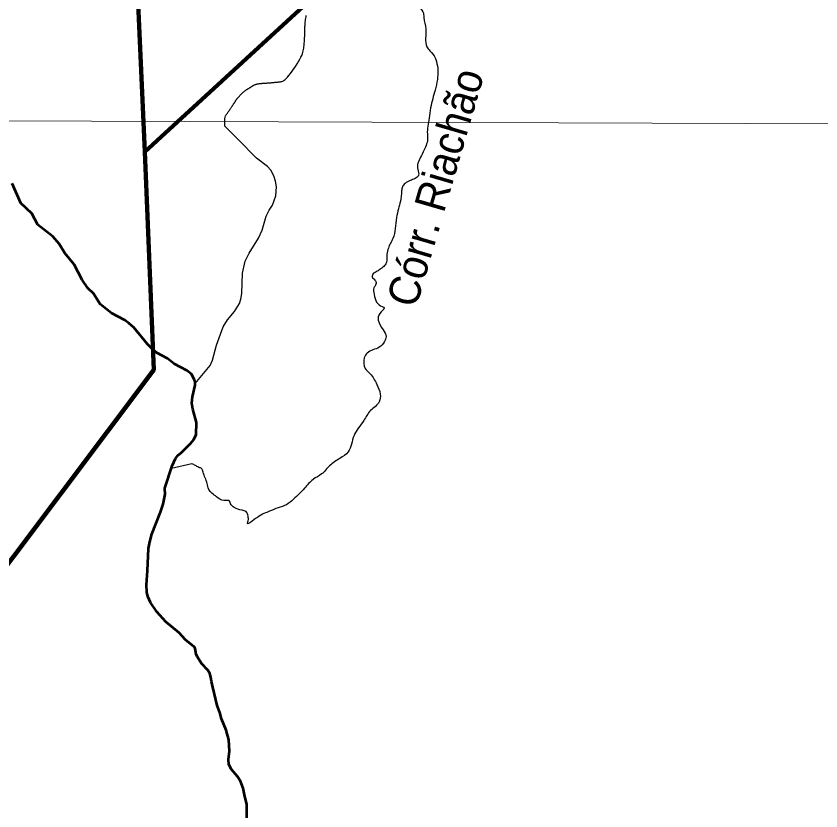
# Model space of a CAD drawing. Extents: x 553962 to 842807, y 8883888 to 9032388.
# Drawn here: x 703445 to 716356, y 8938306 to 8951050 of the extents above; entities that cross this region are included whole.
import ezdxf

# ---------------------------------------------------------------- set-up
doc = ezdxf.new("R2010")
doc.units = 0
doc.header["$LTSCALE"] = 20
for name, color, linetype, lineweight in [('1', 7, 'Continuous', 13), ('24', 7, 'Continuous', 25), ('9', 7, 'Continuous', 90)]:
    doc.layers.add(name, color=color, linetype=linetype, lineweight=lineweight)
doc.layers.add('49', color=7, linetype='Continuous')

msp = doc.modelspace()

# ---------------------------------------------------------------- linework, layer by layer
at = {"layer": '1'}
msp.add_line((565315.27, 8949866.81), (791497.68, 8949052.23), dxfattribs=at)
at = {"layer": '24'}
msp.add_line((706264.71, 8943870.48), (705937.76, 8943795.82), dxfattribs=at)
for points in [[(707335.33, 8949965.78), (707343.36, 8949967.03), (707351.5, 8949968.16), (707359.72, 8949969.19), (707368, 8949970.13), (707376.3, 8949970.99), (707384.61, 8949971.77), (707392.94, 8949972.49), (707401.31, 8949973.15), (707409.73, 8949973.76), (707418.22, 8949974.34), (707426.81, 8949974.89), (707435.51, 8949975.42), (707444.34, 8949975.94), (707453.3, 8949976.45), (707462.39, 8949976.98), (707471.58, 8949977.52), (707480.82, 8949978.09), (707490.11, 8949978.7), (707499.4, 8949979.35), (707508.68, 8949980.06), (707517.91, 8949980.83), (707527.08, 8949981.68), (707536.25, 8949982.59), (707545.5, 8949983.55), (707554.9, 8949984.57), (707564.52, 8949985.61), (707574.43, 8949986.68), (707584.72, 8949987.77), (707595.45, 8949988.86), (707606.67, 8949989.95), (707618.28, 8949991.05), (707630.14, 8949992.16), (707642.14, 8949993.3), (707654.13, 8949994.47), (707666, 8949995.7), (707677.61, 8949996.98), (707688.83, 8949998.33), (707699.63, 8949999.87), (707710.37, 8950002.21), (707721.51, 8950006.03), (707733.52, 8950012.07), (707746.84, 8950021.02), (707761.95, 8950033.6), (707779.31, 8950050.5), (707799.36, 8950072.45), (707822.35, 8950099.85), (707847.63, 8950131.86), (707874.31, 8950167.33), (707901.5, 8950205.14), (707928.34, 8950244.13), (707953.94, 8950283.17), (707977.41, 8950321.12), (707997.88, 8950356.84), (708014.69, 8950389.43), (708028.08, 8950419.07), (708038.49, 8950446.16), (708046.4, 8950471.11), (708052.25, 8950494.34), (708056.51, 8950516.26), (708059.63, 8950537.28), (708062.07, 8950557.81), (708064.21, 8950578.17), (708066.14, 8950598.25), (708067.85, 8950617.86), (708069.37, 8950636.78), (708070.7, 8950654.81), (708071.84, 8950671.75), (708072.8, 8950687.4), (708073.59, 8950701.55), (708074.22, 8950714.07), (708074.7, 8950725.12), (708075.07, 8950734.96), (708075.33, 8950743.81), (708075.52, 8950751.93), (708075.64, 8950759.54), (708075.73, 8950766.9), (708075.79, 8950774.24), (708075.86, 8950781.77), (708075.94, 8950789.6), (708076.04, 8950797.79), (708076.17, 8950806.44), (708076.34, 8950815.6), (708076.57, 8950825.35), (708076.85, 8950835.77), (708077.21, 8950846.93), (708077.66, 8950858.91), (708078.23, 8950871.77), (708078.98, 8950885.59), (708079.95, 8950900.45), (708081.18, 8950916.42), (708082.74, 8950933.57), (708084.66, 8950951.98), (708086.98, 8950971.72), (708089.73, 8950992.81), (708092.74, 8951015.07), (708095.84, 8951038.28), (708098.83, 8951062.2)], [(707103.04, 8949843.33), (707109.6, 8949848.42), (707116.17, 8949853.29), (707122.74, 8949857.98), (707129.33, 8949862.49), (707135.95, 8949866.86), (707142.6, 8949871.13), (707149.3, 8949875.31), (707156.06, 8949879.43), (707162.88, 8949883.52), (707169.76, 8949887.61), (707176.67, 8949891.69), (707183.56, 8949895.75), (707190.39, 8949899.78), (707197.11, 8949903.78), (707203.66, 8949907.73), (707210.02, 8949911.63), (707216.12, 8949915.47), (707221.95, 8949919.23), (707227.54, 8949922.91), (707232.96, 8949926.51), (707238.28, 8949930), (707243.57, 8949933.38), (707248.88, 8949936.64), (707254.28, 8949939.76), (707259.84, 8949942.75), (707265.61, 8949945.59), (707271.6, 8949948.28), (707277.81, 8949950.82), (707284.24, 8949953.21), (707290.89, 8949955.45), (707297.77, 8949957.54), (707304.86, 8949959.48), (707312.18, 8949961.27), (707319.71, 8949962.91), (707327.44, 8949964.41), (707335.33, 8949965.78)], [(707005.53, 8949071.85), (706794.49, 8949287.1), (706791.81, 8949335.96), (706791.81, 8949375.11), (706794.08, 8949405.97), (706798.26, 8949429.95), (706803.94, 8949448.46), (706810.75, 8949462.93), (706818.3, 8949474.75), (706826.2, 8949485.34), (706834.12, 8949495.87), (706841.96, 8949506.49), (706849.65, 8949517.1), (706857.15, 8949527.61), (706864.41, 8949537.91), (706871.38, 8949547.91), (706878, 8949557.52), (706884.22, 8949566.64), (706890.01, 8949575.2), (706895.41, 8949583.23), (706900.47, 8949590.8), (706905.25, 8949597.97), (706909.8, 8949604.82), (706914.18, 8949611.39), (706918.45, 8949617.77), (706922.67, 8949624), (706926.87, 8949630.15), (706931.04, 8949636.22), (706935.15, 8949642.19), (706939.18, 8949648.06), (706943.1, 8949653.83), (706946.88, 8949659.47), (706950.49, 8949664.98), (706953.9, 8949670.36), (706957.11, 8949675.6), (706960.17, 8949680.73), (706963.15, 8949685.79), (706966.13, 8949690.8), (706969.19, 8949695.82), (706972.4, 8949700.88), (706975.82, 8949706), (706979.55, 8949711.24), (706983.63, 8949716.61), (706988.02, 8949722.1), (706992.67, 8949727.71), (706997.53, 8949733.41), (707002.54, 8949739.18), (707007.64, 8949745), (707012.77, 8949750.86), (707017.89, 8949756.74), (707022.95, 8949762.63), (707027.98, 8949768.51), (707033, 8949774.4), (707038.06, 8949780.28), (707043.19, 8949786.16), (707048.44, 8949792.04), (707053.83, 8949797.93), (707059.41, 8949803.8), (707065.2, 8949809.68), (707071.18, 8949815.52), (707077.33, 8949821.31), (707083.62, 8949827.01), (707090.02, 8949832.6), (707096.5, 8949838.05), (707103.04, 8949843.33)], [(706318.13, 8945157.75), (706558.53, 8945449.14), (706593.78, 8945534.08), (706659.09, 8945772.72), (706765.23, 8946065.51), (706837.04, 8946180.29), (706950.78, 8946315.39), (707030.06, 8946442.17), (707051.34, 8946511.72), (707065.53, 8946600.05), (707074.41, 8946928.92), (707120.5, 8947121.76), (707182.67, 8947250.28), (707335.36, 8947487.7), (707390.24, 8947616.93), (707459.21, 8947840.21), (707507.03, 8947940.81), (707556.36, 8948018.23), (707613.41, 8948168.47), (707621.56, 8948310.71), (707609.07, 8948405.14), (707580.34, 8948486.25), (707531.19, 8948578.03), (707480.25, 8948638.26), (707302.29, 8948774.04), (707005.53, 8949071.85)]]:
    msp.add_lwpolyline(points, dxfattribs=at)
at = {"layer": '24', "lineweight": 53}
for points in [[(705832.84, 8943474.06), (705832.25, 8943483.44), (705948.73, 8943839.02), (706001.06, 8943954.51), (706040.19, 8944007.23), (706100.5, 8944053.43), (706243.07, 8944196.48), (706294.62, 8944261.85), (706335.28, 8944339.08), (706341.06, 8944535.41), (706282.44, 8944747.12), (706266.05, 8944843.36), (706272.33, 8944945.56), (706319.27, 8945130.16), (706317, 8945185.35), (706303.96, 8945230.7), (706260.77, 8945306.24), (706182.61, 8945367.1), (705978.73, 8945474.39), (705872.53, 8945557.87), (705704.45, 8945652.52), (705622.37, 8945719.46), (705553.15, 8945790.51), (705334.08, 8946058.71), (705261.14, 8946123.78), (705190.94, 8946173.28), (704977.76, 8946288.61), (704792.63, 8946429.02), (704685.44, 8946599.97), (704597.4, 8946688.7), (704507.14, 8946819.4), (704375.46, 8947069.73), (704224.77, 8947248.33), (704136.74, 8947399.1), (704031.96, 8947515.03), (703791.65, 8947703.97), (703699.7, 8947883.19), (703521.31, 8948048.58), (703380.43, 8948367.76)], [(707112.44, 8938537.61), (707087.72, 8938670.62), (707047.46, 8938783.25), (706998.9, 8938860.14), (706901.05, 8938969.18), (706857.7, 8939050.01), (706854.78, 8939130.07), (706866.72, 8939261.74), (706857.82, 8939446.33), (706814.82, 8939599.79), (706742.16, 8939780.93), (706712.89, 8939886.31), (706669.76, 8939997.22), (706579.57, 8940379.37), (706570.62, 8940449.86), (706551.48, 8940509.27), (706520.24, 8940562.66), (706419.45, 8940668.77), (706347.48, 8940779.51), (706331.35, 8940817.84), (706319.65, 8940908.81), (706302.5, 8940937.07), (706163, 8941049.89), (706059.84, 8941158.75), (705847.86, 8941335.15), (705702.68, 8941495.44), (705602.13, 8941646.25), (705560.76, 8941741.3), (705543.53, 8941811.47), (705536.27, 8941930.57), (705555.45, 8942152.93), (705571.33, 8942515.57), (705588.83, 8942621.53), (705620.58, 8942742.31), (705760.38, 8943097.48), (705802.31, 8943224.23), (705838.49, 8943384.29), (705832.84, 8943474.06)], [(706694.7, 8936277.48), (706830.5, 8936420.38), (706877.21, 8936486.3), (706914.59, 8936562.19), (706925.82, 8936622.03), (706895.34, 8936909.29), (706910.97, 8937033.72), (706943.27, 8937127.24), (707023.24, 8937296.13), (707124.83, 8937469.74), (707160.22, 8937564.47), (707176.93, 8937639.28), (707157.27, 8937927.69), (707160.03, 8938043.54), (707144.19, 8938159.46), (707144.94, 8938415.97), (707112.44, 8938537.61)]]:
    msp.add_lwpolyline(points, dxfattribs=at)
at = {"layer": '24'}
for points in [[(710764.45, 8952700.73), (710808.55, 8952628.53), (710796.52, 8952588.41), (710732.37, 8952468.07), (710692.28, 8952383.84), (710547.94, 8952271.52), (710451.72, 8952187.28), (710375.54, 8952135.13), (710311.39, 8952030.84), (710235.21, 8951906.48), (710171.06, 8951786.14), (710138.99, 8951641.74), (710082.85, 8951517.38), (709994.65, 8951429.13), (709898.42, 8951364.95), (709874.37, 8951284.73), (709890.4, 8951220.54), (709970.59, 8951120.26), (709986.63, 8951028), (710018.7, 8950843.48), (710034.74, 8950558.67), (710082.85, 8950490.48), (710167.05, 8950382.17), (710187.1, 8950322), (710211.15, 8950177.59), (710203.14, 8950033.18), (710167.06, 8949864.71), (710094.89, 8949579.9), (710070.83, 8949411.42), (710042.76, 8949159.91), (710046.77, 8949099.74), (710030.74, 8948999.46), (709990.64, 8948903.19), (709934.51, 8948786.86), (709890.41, 8948690.59), (709890.41, 8948590.3), (709902.44, 8948498.04), (709846.3, 8948445.89), (709766.12, 8948413.8), (709685.93, 8948365.67), (709641.83, 8948313.52), (709629.8, 8948249.34), (709609.75, 8948080.86), (709577.68, 8947960.52), (709549.61, 8947820.12), (709525.55, 8947643.62), (709489.47, 8947483.17), (709449.38, 8947406.95), (709417.3, 8947330.74), (709393.25, 8947226.44), (709385.23, 8947106.1), (709357.16, 8947049.94), (709293.01, 8946997.8), (709236.88, 8946957.68), (709176.74, 8946925.59)], [(709176.74, 8946925.59), (709156.69, 8946869.43), (709176.74, 8946841.35), (709216.83, 8946793.22), (709212.82, 8946737.06), (709184.76, 8946692.93), (709188.77, 8946588.64), (709228.86, 8946464.29), (709268.96, 8946420.16), (709348.27, 8946367.57), (709278.62, 8946282.43), (709255.4, 8946174.08), (709332.79, 8946019.29), (709379.23, 8945910.94), (709356.01, 8945833.55), (709270.88, 8945740.68), (709077.39, 8945647.81), (709030.96, 8945570.41), (709046.43, 8945400.15), (709123.83, 8945315.01), (709232.18, 8945144.75), (709286.36, 8944989.96), (709270.88, 8944866.13), (709131.57, 8944726.82), (709023.22, 8944564.29), (708866.11, 8944324.37), (708770.14, 8944064.33), (708640.12, 8943959.07), (708472.95, 8943838.34), (708346.02, 8943708.31), (708209.81, 8943621.63), (708073.6, 8943479.23), (707894.04, 8943302.77), (707782.6, 8943216.09), (707649.48, 8943166.56), (707510.17, 8943110.84), (707315.14, 8943011.77), (707157.25, 8942921.99), (707169.64, 8942959.14), (707166.54, 8943030.35), (707135.58, 8943104.64), (707070.57, 8943126.31), (706943.65, 8943172.75), (706884.83, 8943231.57), (706869.35, 8943274.91), (706779.57, 8943281.1), (706661.93, 8943343.02), (706587.64, 8943398.74), (706538.1, 8943460.65), (706510.24, 8943556.62), (706445.23, 8943739.27), (706423.56, 8943791.9), (706374.03, 8943813.57), (706321.4, 8943844.53), (706264.71, 8943870.48)]]:
    msp.add_spline(points, degree=3, dxfattribs=at)
at = {"layer": '9'}
for points in [[(705081.22, 8958366.77), (705509.17, 8948874.18), (720755.9, 8962863.64), (723053.57, 8963740.6)], [(705509.17, 8948874.18), (705653.45, 8945380.81), (701918.87, 8940415.34), (694874.03, 8947402.66)]]:
    msp.add_lwpolyline(points, dxfattribs=at)

# ---------------------------------------------------------------- texts
at = {"layer": '49', "width": 0.95}
msp.add_text('Córr. Riachão', height=500, rotation=73.734, dxfattribs=at).set_placement((709860.87, 8946353.1))

doc.saveas('drawing.dxf')
